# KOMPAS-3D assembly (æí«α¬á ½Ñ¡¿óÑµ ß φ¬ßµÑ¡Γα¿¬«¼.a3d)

Referenced files in D:\МОДЕЛЬ ТАНКА Т90\ДЕТАЛИ\ХОДОВАЯ\Ленивец с эксцентриком\: ленивец1.m3d, крышка ленивца внутренняя.m3d, крышка ленивца наружняя.m3d, ось ленивца.m3d, эксцентрик.m3d
Referenced files in D:\МОДЕЛЬ ТАНКА Т90\ДЕТАЛИ\ХОДОВАЯ\Каток опорный с балансиром\: втулка соеденения катков.m3d, шпилька соеденения катков.m3d
Referenced files in D:\МОДЕЛЬ ТАНКА Т90\ДЕТАЛИ\ОБЩИЕ ДЕТАЛИ\: подшипник 13-5-4.m3d, гайка на 5.m3d
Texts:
  Сборка ленивец с эксцентриком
